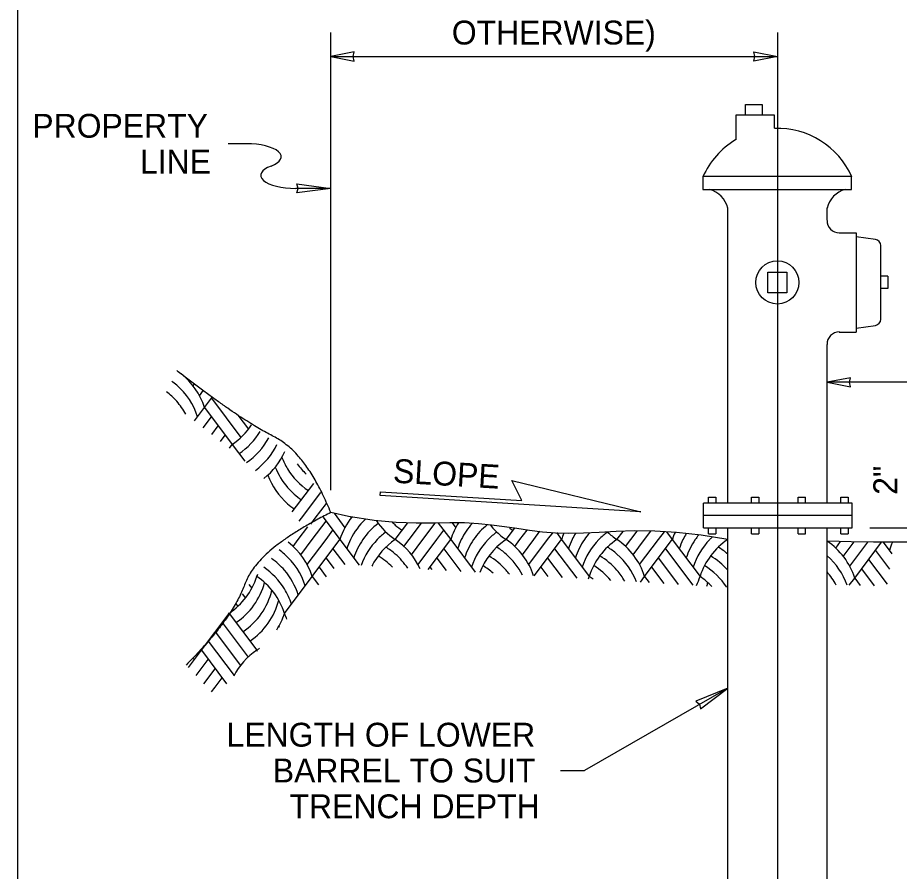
# Model space of a CAD drawing. Extents: x 99862 to 103151, y 100000 to 102076.
# Drawn here: x 99862 to 100453, y 100572 to 101144 of the extents above; entities that cross this region are included whole.
import ezdxf

# ---------------------------------------------------------------- set-up
doc = ezdxf.new("R2010")
doc.units = 0
for name, color, linetype in [('Level 1', 7, 'Continuous'), ('Level 14', 7, 'Continuous'), ('Level 15', 7, 'Continuous'), ('Level 18', 7, 'Continuous'), ('Level 20', 7, 'Continuous'), ('Level 28', 7, 'Continuous'), ('Level 3', 7, 'Continuous'), ('Level 6', 7, 'Continuous'), ('Level 8', 7, 'Continuous')]:
    doc.layers.add(name, color=color, linetype=linetype)

msp = doc.modelspace()

# ---------------------------------------------------------------- linework, layer by layer
at = {"layer": 'Level 1'}
msp.add_lwpolyline([(99862, 99999.5), (103151, 99999.5), (103151, 102075.5), (99862, 102075.5)], close=True, dxfattribs=at)
at = {"layer": 'Level 14'}
for p, q in [((100015.06, 101059.87), (100003.06, 101059.87)), ((100071.79, 101029.87), (100048.36, 101029.87))]:
    msp.add_line(p, q, dxfattribs=at)
msp.add_lwpolyline([(100071.79, 101029.87), (100048.97, 101026.89), (100050.02, 101029.87), (100048.96, 101032.86)], close=True, dxfattribs=at)
for centre, start_param, end_param in [((100015.23, 101051.09), 5.497747, 7.861127), ((100048.36, 101038.66), 2.356226, 4.712389)]:
    msp.add_ellipse(centre, major_axis=(23.43, 0), ratio=0.375, start_param=start_param, end_param=end_param, dxfattribs=at)
at = {"layer": 'Level 15'}
for p, q in [((100071.79, 100827.52), (100071.79, 101134.38)), ((100371.01, 101134.38), (100371.01, 100280.71)), ((100071.79, 101118.38), (100371.01, 101118.38)), ((100667.81, 100899.87), (100404.28, 100899.87)), ((100433.01, 100802.4), (100473.28, 100802.4)), ((100225.77, 100639.59), (100241.77, 100639.59))]:
    msp.add_line(p, q, dxfattribs=at)
for points in [[(100071.79, 101118.38), (100087.52, 101115.3), (100086.79, 101118.38), (100087.52, 101121.47)], [(100371.01, 101118.38), (100355.28, 101115.3), (100356.01, 101118.38), (100355.28, 101121.47)], [(100404.28, 100899.87), (100420.01, 100896.79), (100419.28, 100899.87), (100420.01, 100902.96)], [(100337.75, 100694.86), (100316.49, 100686.03), (100318.9, 100683.97), (100319.47, 100680.86)]]:
    msp.add_lwpolyline(points, close=True, dxfattribs=at)
msp.add_lwpolyline([(100337.75, 100694.86), (100241.77, 100639.59)], dxfattribs=at)
at = {"layer": 'Level 18'}
for p, q in [((100369.16, 101079.01), (100343.09, 101079.01)), ((100343.09, 101079.01), (100343.09, 101062.53)), ((100369.16, 101070.25), (100369.16, 101079.01)), ((100337.76, 100818.9), (100337.76, 101016.77)), ((100404.28, 101008.55), (100404.28, 101016.77)), ((100412.48, 101000.03), (100423.71, 101000.03)), ((100423.71, 101000.03), (100423.71, 100933.52)), ((100423.71, 100997.62), (100436.72, 100995.77)), ((100440.14, 100991.52), (100440.14, 100942.31)), ((100444.98, 100971.05), (100440.14, 100971.05)), ((100444.98, 100971.05), (100444.98, 100962.81)), ((100444.98, 100962.81), (100440.14, 100962.81)), ((100423.71, 100936.2), (100436.72, 100938.05)), ((100412.48, 100933.52), (100423.71, 100933.52)), ((100404.28, 100818.9), (100404.28, 100925.28)), ((100324.91, 100822.97), (100329.87, 100822.97)), ((100324.91, 100818.9), (100324.91, 100822.97)), ((100329.87, 100822.97), (100329.87, 100818.9)), ((100353.71, 100822.93), (100358.67, 100822.93)), ((100353.71, 100818.9), (100353.71, 100822.93)), ((100358.67, 100822.93), (100358.67, 100818.9)), ((100384.88, 100822.97), (100389.84, 100822.97)), ((100384.88, 100818.9), (100384.88, 100822.97)), ((100389.84, 100818.9), (100389.84, 100822.97)), ((100413.47, 100822.91), (100418.39, 100822.91)), ((100413.47, 100818.9), (100413.47, 100822.91)), ((100418.39, 100822.91), (100418.39, 100818.83)), ((100421.02, 100818.9), (100321.54, 100818.9)), ((100321.54, 100802.4), (100321.54, 100818.9)), ((100421.02, 100802.4), (100421.02, 100818.9)), ((100421.02, 100810.67), (100321.54, 100810.67)), ((100321.54, 100802.4), (100421.02, 100802.4)), ((100324.91, 100798.3), (100324.91, 100802.4)), ((100329.87, 100802.4), (100329.87, 100798.3)), ((100353.71, 100798.3), (100353.71, 100802.4)), ((100358.67, 100802.4), (100358.67, 100798.3)), ((100384.88, 100798.33), (100384.88, 100802.4)), ((100389.84, 100798.33), (100389.84, 100802.4)), ((100413.47, 100798.27), (100413.47, 100802.4)), ((100418.39, 100802.4), (100418.39, 100798.27)), ((100324.91, 100798.3), (100329.87, 100798.3)), ((100353.71, 100798.3), (100358.67, 100798.3)), ((100384.88, 100798.33), (100389.84, 100798.33)), ((100413.47, 100798.27), (100418.39, 100798.27))]:
    msp.add_line(p, q, dxfattribs=at)
msp.add_lwpolyline([(100349.73, 101079.01), (100349.73, 101086.22), (100360.92, 101086.22), (100360.92, 101079.01)], dxfattribs=at)
for points in [[(100420.74, 101029.26), (100420.74, 101037.77), (100320.98, 101037.77), (100320.98, 101029.26)], [(100364.62, 100959.85), (100364.62, 100973.7), (100377.38, 100973.7), (100377.38, 100959.85)]]:
    msp.add_lwpolyline(points, close=True, dxfattribs=at)
msp.add_circle((100371.01, 100966.85), 14.47, dxfattribs=at)
for centre, radius, start, end in [((100371.01, 101015.62), 54.54, 23.89556, 91.97586), ((100371.01, 101015.62), 54.54, 120.92859, 156.10444), ((100320.83, 101012.49), 17.46, 14.112, 73.77865), ((100421.2, 101012.49), 17.46, 106.22135, 165.888), ((100412.57, 101008.41), 8.31, 180, 270), ((100436.11, 100991.53), 4.16, 0, 81.50484), ((100436.11, 100942.18), 4.16, 278.49516, 0), ((100412.57, 100925.3), 8.31, 90, 180)]:
    msp.add_arc(centre, radius, start, end, dxfattribs=at)
at = {"layer": 'Level 28'}
for p, q in [((99974.44, 100903.12), (99974.62, 100903.36)), ((99979.53, 100897.54), (99980.62, 100898.99)), ((99983.84, 100890.9), (99986.62, 100894.62)), ((99987.18, 100882.99), (99992.63, 100890.25)), ((99991.82, 100889.17), (100011.56, 100862.85)), ((99980.41, 100873.96), (99987.18, 100882.99)), ((99987.18, 100882.99), (100005.74, 100858.24)), ((99986.28, 100869.4), (99991.82, 100876.8)), ((100009.54, 100877.92), (100016.66, 100868.43)), ((99992.14, 100864.85), (99996.46, 100870.61)), ((99998.01, 100860.3), (100001.1, 100864.42)), ((100003.87, 100855.75), (100005.74, 100858.24)), ((100005.74, 100858.24), (100014.2, 100846.97)), ((100050.51, 100843.68), (100050.7, 100843.93)), ((100046.01, 100812.93), (100060.37, 100832.08)), ((100052.15, 100808.74), (100065.08, 100825.99)), ((100061.43, 100808.74), (100068.84, 100818.63)), ((100073.99, 100812.03), (100081.24, 100802.36)), ((100050.65, 100806.74), (100052.15, 100808.74)), ((100058.37, 100804.66), (100061.43, 100808.74)), ((100059.34, 100794.45), (100068.62, 100806.82)), ((100066.71, 100809.37), (100077.9, 100794.45)), ((100085.05, 100809.66), (100085.55, 100809)), ((100115.02, 100794.45), (100123.36, 100805.57)), ((100124.3, 100794.45), (100132.49, 100805.36)), ((100133.58, 100794.45), (100141.85, 100805.46)), ((100143.86, 100805.49), (100152.14, 100794.45)), ((100153.05, 100805.61), (100155.49, 100802.36)), ((100050.06, 100794.45), (100056.51, 100803.05)), ((100068.62, 100794.45), (100073.26, 100800.63)), ((100142.86, 100794.45), (100147.5, 100800.63)), ((100189.27, 100794.45), (100194.87, 100801.91)), ((100198.55, 100794.45), (100203.28, 100800.76)), ((100207.83, 100794.45), (100211.97, 100799.96)), ((100217.11, 100794.45), (100220.72, 100799.26)), ((100222.92, 100799.08), (100226.39, 100794.45)), ((100263.51, 100794.45), (100267.63, 100799.94)), ((100272.79, 100794.45), (100276.97, 100800.02)), ((100282.07, 100794.45), (100286.26, 100800.03)), ((100291.35, 100794.45), (100295.28, 100799.68)), ((100296.78, 100799.59), (100300.63, 100794.45)), ((100046.59, 100789.83), (100050.06, 100794.45)), ((100051.69, 100784.25), (100059.34, 100794.45)), ((100056, 100777.62), (100068.62, 100794.45)), ((100059.34, 100769.7), (100077.9, 100794.45)), ((100077.9, 100794.45), (100090.85, 100777.18)), ((100120.84, 100789.83), (100124.3, 100794.45)), ((100125.94, 100784.25), (100133.58, 100794.45)), ((100130.24, 100777.62), (100142.86, 100794.45)), ((100137.12, 100774.41), (100152.14, 100794.45)), ((100152.14, 100794.45), (100168.58, 100772.53)), ((100195.08, 100789.83), (100198.55, 100794.45)), ((100200.18, 100784.25), (100207.83, 100794.45)), ((100204.49, 100777.62), (100217.11, 100794.45)), ((100208.17, 100770.16), (100226.39, 100794.45)), ((100226.39, 100794.45), (100244.95, 100769.7)), ((100269.33, 100789.83), (100272.79, 100794.45)), ((100274.43, 100784.25), (100282.07, 100794.45)), ((100278.73, 100777.62), (100291.35, 100794.45)), ((100282.07, 100769.7), (100300.63, 100794.45)), ((100300.63, 100794.45), (100319.2, 100769.7)), ((100410.1, 100788.75), (100413.34, 100793.08)), ((100415.2, 100783.18), (100422.43, 100792.82)), ((100419.5, 100776.54), (100431.63, 100792.72)), ((100422.84, 100768.62), (100440.84, 100792.61)), ((100441.98, 100792.6), (100447.75, 100784.91)), ((100073.26, 100788.26), (100081.13, 100777.76)), ((100147.5, 100788.26), (100158.87, 100773.11)), ((100221.75, 100788.26), (100236.6, 100768.46)), ((100295.99, 100788.26), (100314.34, 100763.8)), ((100436.76, 100787.19), (100446.15, 100774.67)), ((100068.62, 100782.07), (100073.9, 100775.04)), ((100142.86, 100782.07), (100149.15, 100773.69)), ((100217.11, 100782.07), (100226.89, 100769.04)), ((100291.35, 100782.07), (100304.62, 100764.38)), ((100432.12, 100781), (100444.54, 100764.44)), ((100063.98, 100775.89), (100068.76, 100769.51)), ((100138.22, 100775.89), (100139.43, 100774.27)), ((100212.47, 100775.89), (100217.17, 100769.62)), ((100286.71, 100775.89), (100294.9, 100764.97)), ((100427.48, 100774.81), (100435.95, 100763.52)), ((100021.86, 100770.18), (100022.22, 100769.7)), ((100040.78, 100744.95), (100059.34, 100769.7)), ((100059.34, 100769.7), (100063.62, 100763.99)), ((100279.23, 100765.9), (100282.07, 100769.7)), ((100282.07, 100769.7), (100285.19, 100765.55)), ((100016.98, 100764.3), (100018.87, 100761.78)), ((100419.22, 100763.8), (100422.84, 100768.62)), ((100422.84, 100768.62), (100426.56, 100763.67)), ((100012.43, 100757.99), (100014.57, 100755.15)), ((100007.89, 100751.68), (100009.47, 100749.57)), ((100003.34, 100745.37), (100003.65, 100744.95)), ((99985.09, 100720.2), (100003.65, 100744.95)), ((100003.65, 100744.95), (100022.22, 100720.2)), ((99999.01, 100738.76), (100016.4, 100715.58)), ((99994.37, 100732.58), (100011.3, 100710)), ((99989.73, 100726.39), (100007, 100703.37)), ((99976.47, 100708.71), (99985.09, 100720.2)), ((99985.09, 100720.2), (100001.94, 100697.73)), ((99981.65, 100703.23), (99989.73, 100714.01)), ((99986.82, 100697.76), (99994.37, 100707.83)), ((99994.37, 100695.45), (99999.01, 100701.64)), ((99991.99, 100692.28), (99994.37, 100695.45))]:
    msp.add_line(p, q, dxfattribs=at)
for centre, start, end in [((99994.82, 100868.75), 123.90404, 123.90495), ((99942.42, 100868.75), 56.08421, 56.09573), ((99942.42, 100868.75), 17.6434, 51.76701), ((99937.78, 100862.56), 48.95968, 54.26438), ((99933.14, 100856.37), 40.94134, 52.42136), ((99937.78, 100862.56), 17.6434, 48.95975), ((99933.14, 100856.37), 28.06951, 40.94141), ((99979.54, 100897.22), 303.90361, 326.44558), ((99984.18, 100891.04), 303.90361, 329.21926), ((99988.82, 100884.85), 304.27416, 331.76659), ((99993.46, 100878.66), 306.34246, 334.24492), ((99998.1, 100872.47), 308.01718, 336.01166), ((100082.99, 100866.29), 200.87781, 211.33197), ((100078.35, 100860.1), 201.43438, 220.94161), ((100082.99, 100866.29), 211.33188, 236.09639), ((100087.63, 100872.47), 215.44432, 226.55916), ((100073.71, 100853.91), 200.24322, 228.95992), ((100078.35, 100860.1), 220.94154, 236.09639), ((100073.71, 100853.91), 228.95986, 236.09639), ((100122.66, 100780.21), 141.39378, 162.3566), ((100127.3, 100774.02), 133.46987, 154.2266), ((100131.94, 100767.84), 127.1006, 145.49109), ((100141.22, 100833.43), 214.14534, 236.09639), ((100145.86, 100839.62), 225.51765, 228.95992), ((100196.91, 100780.21), 147.26638, 162.3566), ((100201.55, 100774.02), 138.21479, 154.2266), ((100206.19, 100767.84), 128.96048, 145.49109), ((100136.58, 100761.65), 126.331, 135.71278), ((100145.86, 100839.62), 228.95986, 236.09639), ((100210.83, 100761.65), 126.331, 135.71278), ((100215.47, 100833.43), 218.64568, 230.83364), ((100220.11, 100839.62), 232.46241, 236.09639), ((100271.15, 100780.21), 156.85489, 162.3566), ((100275.79, 100774.02), 148.48666, 154.2266), ((100280.43, 100767.84), 138.49582, 145.49109), ((100285.07, 100761.65), 126.36274, 135.71278), ((100289.71, 100833.43), 226.29606, 236.09639), ((100345.4, 100780.21), 156.05062, 162.3566), ((100350.04, 100774.02), 148.61433, 154.2266), ((100014.58, 100755.46), 17.6434, 52.22548), ((100127.3, 100774.02), 154.22654, 162.3566), ((100131.94, 100767.84), 145.49102, 162.3566), ((100136.58, 100761.65), 135.71269, 160.79455), ((100141.22, 100755.46), 123.90361, 153.15099), ((100088.82, 100755.46), 24.23123, 56.09634), ((100201.55, 100774.02), 154.22654, 162.3566), ((100206.19, 100767.84), 145.49102, 162.3566), ((100210.83, 100761.65), 135.71269, 162.3566), ((100215.47, 100755.46), 124.95971, 158.93313), ((100215.47, 100833.43), 230.83364, 236.09639), ((100215.47, 100755.46), 123.90361, 124.95971), ((100163.07, 100755.46), 18.27197, 56.09634), ((100275.79, 100774.02), 154.22654, 162.3566), ((100280.43, 100767.84), 145.49102, 162.3566), ((100285.07, 100761.65), 135.71269, 162.3566), ((100289.71, 100755.46), 123.90361, 162.3566), ((100237.31, 100755.46), 17.6434, 56.09634), ((100350.04, 100774.02), 154.22654, 162.3566), ((100354.68, 100767.84), 145.49102, 162.3566), ((100359.32, 100761.65), 135.71269, 162.3566), ((100354.68, 100767.84), 141.09014, 145.49109), ((100363.96, 100755.46), 123.9045, 162.3566), ((100359.32, 100761.65), 133.01819, 135.71278), ((100363.96, 100755.46), 123.90361, 123.9045), ((100430.48, 100754.39), 123.90361, 123.90451), ((100378.08, 100754.39), 56.09552, 56.09634), ((100378.08, 100754.39), 17.6434, 56.09552), ((100490.81, 100772.95), 155.27178, 162.3566), ((100009.94, 100749.27), 48.95968, 54.40953), ((100084.18, 100749.27), 48.95968, 58.54646), ((100158.43, 100749.27), 48.95968, 58.54646), ((100232.67, 100749.27), 48.95968, 58.54646), ((100306.92, 100749.27), 48.96078, 58.54646), ((100005.3, 100743.09), 40.94134, 55.21207), ((100009.94, 100749.27), 17.6434, 48.95975), ((100079.54, 100743.09), 44.21699, 59.30215), ((100084.18, 100749.27), 33.55655, 48.95975), ((100153.79, 100743.09), 40.94134, 59.30215), ((100158.43, 100749.27), 27.04515, 48.95975), ((100228.03, 100743.09), 40.94134, 59.30215), ((100232.67, 100749.27), 20.94461, 48.95975), ((100302.28, 100743.09), 40.9426, 59.30215), ((100373.44, 100748.2), 19.4248, 48.95975), ((100000.66, 100736.9), 31.33163, 56.01598), ((100074.9, 100736.9), 57.77943, 58.48737), ((100149.15, 100736.9), 48.00745, 58.48737), ((100223.39, 100736.9), 39.99999, 58.48737), ((100297.64, 100736.9), 32.94061, 58.48737), ((99977.45, 100783.94), 303.90361, 342.3566), ((100066.98, 100755.46), 160.53199, 162.3566), ((99996.02, 100730.71), 17.6434, 56.09639), ((100005.3, 100743.09), 17.6434, 40.94141), ((100153.79, 100743.09), 36.70183, 40.94141), ((100200.19, 100783.94), 340.15732, 342.3566), ((100218.75, 100730.71), 52.14305, 56.09639), ((100228.03, 100743.09), 29.94292, 40.94141), ((100274.43, 100783.94), 334.42061, 342.3566), ((100293, 100730.71), 43.48895, 56.09639), ((100368.8, 100742.01), 27.83434, 40.94141), ((99982.09, 100777.75), 303.90361, 345.01126), ((100279.07, 100777.75), 342.00735, 345.01126), ((99986.73, 100771.56), 303.90361, 346.31988), ((100000.65, 100736.9), 17.6434, 31.33172), ((99991.38, 100765.37), 303.90361, 345.77133), ((99996.02, 100759.19), 327.39306, 342.3566), ((100085.54, 100759.19), 197.64354, 202.76467), ((100080.9, 100753), 200.87781, 201.66302), ((100011.29, 100759.19), 236.03653, 236.09639), ((100048.42, 100681.22), 123.90361, 152.51833), ((99996.02, 100759.19), 303.90361, 306.71404), ((100066.98, 100734.44), 197.6434, 198.29794), ((100006.65, 100753), 234.84855, 236.09639)]:
    msp.add_arc(centre, 46.97, start, end, dxfattribs=at)
at = {"layer": 'Level 3'}
msp.add_lwpolyline([(100105.03, 100826.45), (100199.82, 100820.53), (100193.17, 100833.93), (100279.53, 100813.08), (100104.87, 100823.98)], close=True, dxfattribs=at)
at = {"layer": 'Level 6'}
for p, q in [((100337.76, 100510.87), (100337.76, 100802.4)), ((100404.28, 100510.87), (100404.28, 100802.4))]:
    msp.add_line(p, q, dxfattribs=at)
at = {"layer": 'Level 8'}
for points in [[(100337.76, 100794.45), (100319.94, 100797.35), (100303.47, 100799.22), (100288.82, 100800.03), (100275.26, 100800.27), (100263.04, 100799.75), (100251.61, 100799.22), (100241.22, 100798.7), (100231.38, 100798.4), (100222.34, 100798.7), (100213.56, 100799.47), (100205.04, 100800.52), (100196.53, 100801.88), (100188.29, 100802.96), (100179.51, 100804.01), (100170.76, 100805.08), (100161.41, 100805.61), (100151.61, 100805.61), (100140.97, 100805.36), (100129.01, 100805.36), (100115.68, 100805.86), (100100.78, 100807.21), (100083.77, 100809.86), (100071.79, 100812.52)], [(100461.72, 100792.6), (100448.96, 100792.6), (100435.39, 100792.6), (100420.49, 100792.85), (100404.28, 100793.37)]]:
    msp.add_lwpolyline(points, dxfattribs=at)
for points in [[(100071.79, 100812.52), (100055.86, 100852.42), (100010.66, 100875), (99968.62, 100907.73)], [(100071.79, 100812.52), (100022.64, 100788.06), (100005.93, 100741.37), (99974.94, 100710.32)]]:
    msp.add_open_spline(points, degree=2, dxfattribs=at)

# ---------------------------------------------------------------- texts
at = {"layer": 'Level 20'}
for s, p in [('OTHERWISE)', (100152.88, 101126.38)), ('PROPERTY', (99871.82, 101063.87)), ('LINE', (99943.96, 101039.87)), ('LENGTH OF LOWER', (100001.93, 100655.59)), ('BARREL TO SUIT', (100032.95, 100631.59)), ('TRENCH DEPTH', (100044.15, 100607.59))]:
    msp.add_text(s, height=16, dxfattribs=at).set_placement(p)
for s, rotation, p in [('SLOPE', 356.67688, (100113.23, 100832.65)), ('2"', 90, (100451.29, 100824.46))]:
    msp.add_text(s, height=16, rotation=rotation, dxfattribs=at).set_placement(p)

doc.saveas('drawing.dxf')
